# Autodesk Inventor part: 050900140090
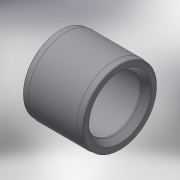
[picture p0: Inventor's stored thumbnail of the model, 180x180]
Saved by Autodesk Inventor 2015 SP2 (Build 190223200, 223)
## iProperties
Created: 2017-11
Part Number: 050900140090
Material: Generic
Description: PLASSON BUSHING-CEMENT PVC 140-90
Document SubType Name: Modeling
Designer: KIM
Density: 1 g/cm^3
Appearance: Default
Author: KIM
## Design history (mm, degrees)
derived "050900.ipt"
feature "Solid1::050900.ipt"
tag "TaggingFeature1"
body "Solid1"
other parameters: "d2" = 51, "d3" = 76, "d7" = 7.6, "d11" = 7.6, "d12" = 1.4, "d14" = 1.4, "d15" = 7.6, "d17" = 1.4, "d18" = 1.4, "d19" = 80.1, "d20" = 5, "d21" = 17.97, "L_" = 76, "l_" = 51, "z_" = 2
